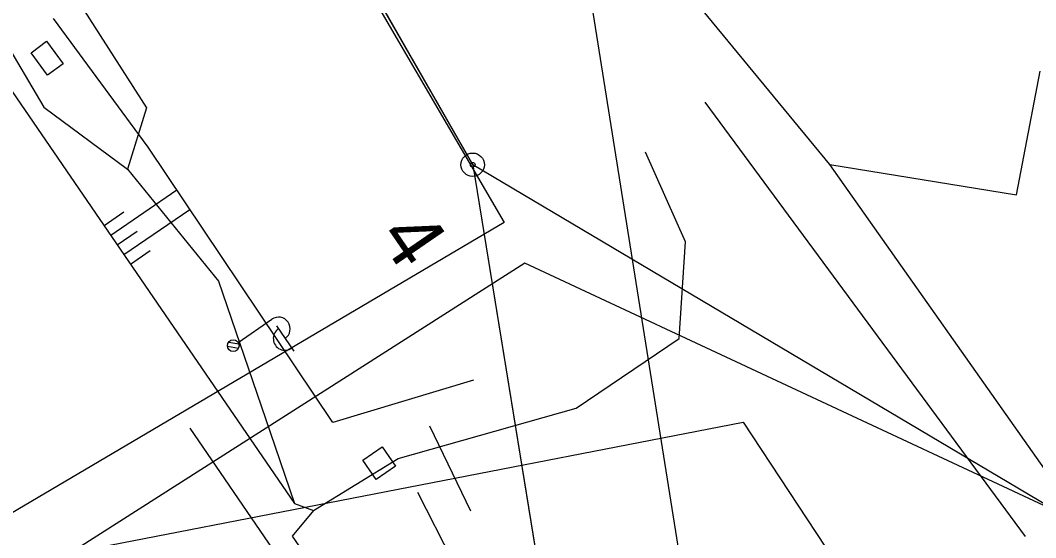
# Model space of a CAD drawing. Extents: x -469926 to -462499, y -1098642 to -1092733.
# Drawn here: x -465877.06 to -465833.7, y -1094388.4 to -1094366.3 of the extents above; entities that cross this region are included whole.
import ezdxf

# ---------------------------------------------------------------- set-up
doc = ezdxf.new("R2010")
doc.units = 0
for name, color, linetype in [('Vrstva 1', 7, 'Continuous'), ('Vrstva 10', 7, 'Continuous'), ('Vrstva 13', 7, 'Continuous'), ('Vrstva 14', 7, 'Continuous'), ('Vrstva 16', 7, 'Continuous'), ('Vrstva 24', 7, 'Continuous'), ('Vrstva 40', 7, 'Continuous'), ('Vrstva 6', 7, 'Continuous'), ('Vrstva 62', 7, 'Continuous'), ('Vrstva 7', 7, 'Continuous'), ('Vrstva 8', 7, 'Continuous')]:
    doc.layers.add(name, color=color, linetype=linetype)

msp = doc.modelspace()

# ---------------------------------------------------------------- linework, layer by layer
at = {"layer": 'Vrstva 1'}
for p, q in [((-465857.74, -1094372.47), (-465885.11, -1094324.68)), ((-465842.49, -1094372.46), (-465855.21, -1094357.03)), ((-465842.49, -1094372.46), (-465855.21, -1094357.03)), ((-465834.52, -1094373.75), (-465833.5, -1094368.47)), ((-465834.52, -1094373.75), (-465833.5, -1094368.47)), ((-465831.51, -1094388.03), (-465857.74, -1094372.47)), ((-465857.74, -1094372.47), (-465854.79, -1094390.59)), ((-465831.51, -1094388.03), (-465857.74, -1094372.47)), ((-465857.74, -1094372.47), (-465854.79, -1094390.59)), ((-465831.51, -1094388.03), (-465842.49, -1094372.46)), ((-465842.49, -1094372.46), (-465834.52, -1094373.75)), ((-465831.51, -1094388.03), (-465842.49, -1094372.46)), ((-465842.49, -1094372.46), (-465834.52, -1094373.75))]:
    msp.add_line(p, q, dxfattribs=at)
at = {"layer": 'Vrstva 10'}
msp.add_lwpolyline([(-465989.75, -1094172.94), (-465988.81, -1094177.38), (-465966.26, -1094209.73), (-465965.16, -1094211.3), (-465925.78, -1094266.9), (-465885.11, -1094324.68), (-465857.74, -1094372.47), (-465854.79, -1094390.59)], dxfattribs=at)
at = {"layer": 'Vrstva 13'}
for p, q in [((-465847.827, -1094369.795), (-465834.147, -1094388.342)), ((-465847.827, -1094369.795), (-465834.147, -1094388.342)), ((-465848.658, -1094375.765), (-465850.363, -1094371.941)), ((-465848.658, -1094375.765), (-465850.363, -1094371.941)), ((-465848.925, -1094379.897), (-465848.658, -1094375.765)), ((-465848.925, -1094379.897), (-465848.658, -1094375.765)), ((-465853.32, -1094382.868), (-465848.925, -1094379.897)), ((-465853.32, -1094382.868), (-465848.925, -1094379.897)), ((-465860.916, -1094385.018), (-465853.32, -1094382.868)), ((-465860.916, -1094385.018), (-465853.32, -1094382.868)), ((-465864.543, -1094387.233), (-465860.916, -1094385.018)), ((-465864.543, -1094387.233), (-465865.447, -1094388.333))]:
    msp.add_line(p, q, dxfattribs=at)
at = {"layer": 'Vrstva 14'}
for p, q in [((-465885.778, -1094324.629), (-465856.392, -1094374.932)), ((-465853.448, -1094360.64), (-465848.124, -1094394.138)), ((-465853.448, -1094360.64), (-465848.124, -1094394.138)), ((-465856.392, -1094374.932), (-465889.696, -1094394.582)), ((-465891.198, -1094392.196), (-465846.188, -1094383.458)), ((-465846.188, -1094383.458), (-465812.309, -1094434.918)), ((-465846.188, -1094383.458), (-465812.309, -1094434.918)), ((-465865.447, -1094388.333), (-465864.436, -1094389.802))]:
    msp.add_line(p, q, dxfattribs=at)
at = {"layer": 'Vrstva 16'}
msp.add_lwpolyline([(-465861.601, -1094384.516), (-465861.035, -1094385.34), (-465861.859, -1094385.906), (-465862.425, -1094385.082), (-465861.601, -1094384.516)], dxfattribs=at)
at = {"layer": 'Vrstva 24'}
for radius in [0.5, 0.5, 0.1, 0.1]:
    msp.add_circle((-465857.74, -1094372.47), radius, dxfattribs=at)
at = {"layer": 'Vrstva 40'}
for p, q in [((-465859.582, -1094383.624), (-465857.836, -1094387.242)), ((-465859.582, -1094383.624), (-465857.836, -1094387.242)), ((-465860.09, -1094386.445), (-465858.183, -1094390.217)), ((-465860.09, -1094386.445), (-465858.183, -1094390.217))]:
    msp.add_line(p, q, dxfattribs=at)
at = {"layer": 'Vrstva 6'}
for p, q in [((-465867.758, -1094380.057), (-465866.316, -1094379.066)), ((-465866.118, -1094379.354), (-465865.381, -1094380.425)), ((-465868.212, -1094380.223), (-465867.741, -1094380.31)), ((-465868.159, -1094380.043), (-465867.727, -1094380.123)), ((-465869.821, -1094383.716), (-465866.271, -1094388.9))]:
    msp.add_line(p, q, dxfattribs=at)
msp.add_circle((-465867.964, -1094380.198), 0.25, dxfattribs=at)
msp.add_circle((-465867.964, -1094380.198), 0.25, dxfattribs=at)
for centre, start, end in [((-465866.033, -1094379.477), 304.4976, 124.4976), ((-465865.754, -1094379.893), 123.795, 305.2002)]:
    msp.add_arc(centre, 0.5, start, end, dxfattribs=at)
at = {"layer": 'Vrstva 62'}
for p, q in [((-465875.038, -1094364.786), (-465871.666, -1094370.046)), ((-465871.6, -1094371.72), (-465875.642, -1094366.227)), ((-465877.836, -1094366.991), (-465876.053, -1094370.01)), ((-465876.589, -1094367.699), (-465875.938, -1094367.197)), ((-465875.938, -1094367.197), (-465875.222, -1094368.157)), ((-465875.9, -1094368.651), (-465876.589, -1094367.699)), ((-465875.222, -1094368.157), (-465875.9, -1094368.651)), ((-465877.75, -1094368.84), (-465871.55, -1094377.885)), ((-465876.053, -1094370.01), (-465872.481, -1094372.654)), ((-465871.666, -1094370.046), (-465872.481, -1094372.654)), ((-465867.659, -1094377.599), (-465871.6, -1094371.72)), ((-465872.481, -1094372.654), (-465868.59, -1094377.443)), ((-465873.199, -1094375.479), (-465870.377, -1094373.545)), ((-465873.481, -1094375.068), (-465872.633, -1094374.486)), ((-465872.633, -1094376.305), (-465869.82, -1094374.376)), ((-465872.916, -1094375.892), (-465872.07, -1094375.313)), ((-465872.351, -1094376.717), (-465871.508, -1094376.139)), ((-465868.59, -1094377.443), (-465866.587, -1094383.304)), ((-465863.718, -1094383.478), (-465867.659, -1094377.599)), ((-465871.55, -1094377.885), (-465865.35, -1094386.93)), ((-465857.71, -1094381.67), (-465863.718, -1094383.478)), ((-465866.587, -1094383.304), (-465865.35, -1094386.93)), ((-465865.35, -1094386.93), (-465864.543, -1094387.233))]:
    msp.add_line(p, q, dxfattribs=at)
at = {"layer": 'Vrstva 8'}
for p, q in [((-465855.516, -1094376.677), (-465902.727, -1094406.775)), ((-465803.103, -1094401.157), (-465855.516, -1094376.677)), ((-465803.103, -1094401.157), (-465855.516, -1094376.677))]:
    msp.add_line(p, q, dxfattribs=at)

# ---------------------------------------------------------------- texts
at = {"layer": 'Vrstva 7'}
msp.add_text('4', height=2.5, rotation=304.4976, dxfattribs=at).set_placement((-465861.823, -1094375.544))

doc.saveas('drawing.dxf')
